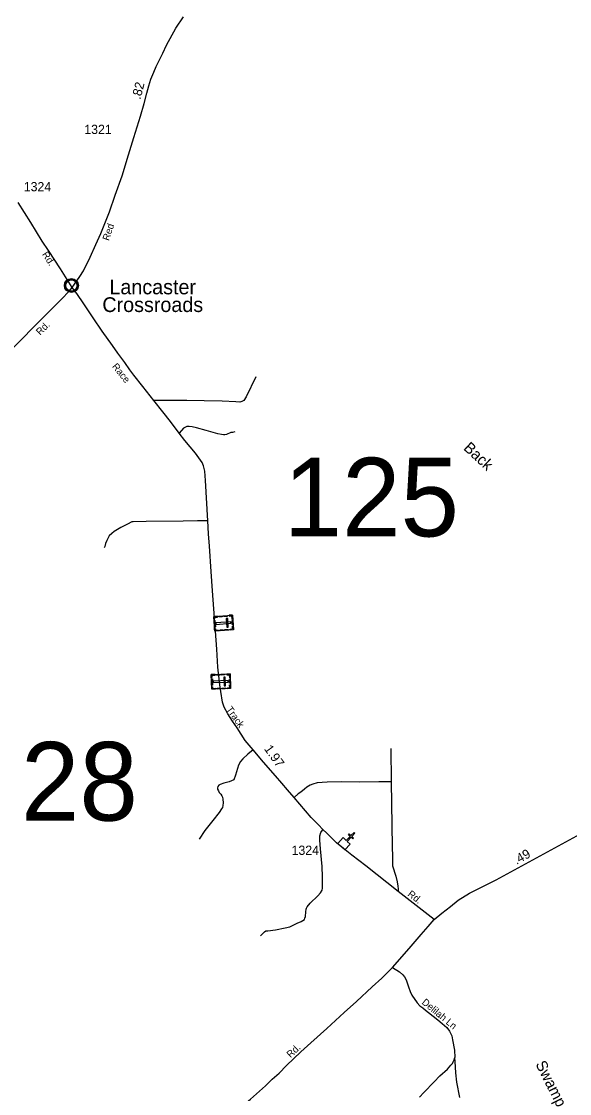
# Model space of a CAD drawing. Extents: x 2220236 to 2384410, y 720751 to 894131.
# Drawn here: x 2270444 to 2277880, y 831981 to 846519 of the extents above; entities that cross this region are included whole.
import ezdxf

# ---------------------------------------------------------------- set-up
doc = ezdxf.new("R2010")
doc.units = 0
doc.layers.add('Default', color=7, linetype='Continuous')

msp = doc.modelspace()

# ---------------------------------------------------------------- linework, layer by layer
at = {"layer": 'Default'}
msp.add_line((2275457, 836661), (2275461, 836207), dxfattribs=at)
for points in [[(2271133, 842913), (2271166, 842957), (2271237, 843061), (2271284, 843139), (2271378, 843322), (2271452, 843494), (2271520, 843644), (2271639, 843936), (2271717, 844164), (2271812, 844426), (2271898, 844711), (2271968, 844945), (2272015, 845092), (2272058, 845233), (2272107, 845406), (2272147, 845548), (2272172, 845646), (2272201, 845738), (2272239, 845832), (2272272, 845910), (2272362, 846091), (2272414, 846196), (2272538, 846429), (2272643, 846583)], [(2271133, 842913), (2270972, 843165), (2270812, 843415), (2270726, 843540), (2270574, 843793), (2270401, 844062)], [(2268432, 839884), (2268447, 839914), (2268479, 839958), (2268522, 840025), (2268605, 840135), (2268829, 840415), (2268931, 840536), (2269007, 840629), (2269178, 840846), (2269254, 840937), (2269443, 841177), (2269642, 841393), (2269800, 841551), (2269954, 841710), (2270098, 841859), (2270245, 842006), (2270400, 842161), (2270653, 842420), (2270813, 842577), (2270938, 842704), (2271017, 842782), (2271063, 842833), (2271095, 842865), (2271133, 842913)], [(2276045, 834343), (2275553, 834723), (2275115, 835071), (2274925, 835214), (2274815, 835303), (2274719, 835379), (2274581, 835517), (2274539, 835559), (2274471, 835628), (2274376, 835724), (2274142, 835997), (2274055, 836098), (2273978, 836191), (2273889, 836291), (2273727, 836474), (2273589, 836640), (2273481, 836769), (2273369, 836941), (2273306, 837029), (2273245, 837128), (2273196, 837220), (2273172, 837289), (2273147, 837431), (2273135, 837522), (2273108, 837763), (2273093, 838008), (2273036, 838800), (2273020, 839061), (2272996, 839402), (2272984, 839569), (2272972, 839749), (2272942, 840293), (2272932, 840423), (2272915, 840493), (2272895, 840540), (2272873, 840570), (2272807, 840665), (2272734, 840752), (2272659, 840837), (2272582, 840936), (2272465, 841094), (2272363, 841227), (2272242, 841380), (2272091, 841570), (2271969, 841724), (2271917, 841795), (2271847, 841895), (2271754, 842019), (2271679, 842124), (2271541, 842321), (2271416, 842498), (2271292, 842689), (2271195, 842828), (2271133, 842913)], [(2273622, 841702), (2273491, 841427), (2273460, 841378), (2273434, 841364), (2273405, 841358), (2273351, 841360), (2273169, 841368), (2272925, 841375), (2272690, 841381), (2272510, 841379), (2272242, 841380)], [(2273340, 840952), (2273308, 840945), (2273286, 840943), (2273226, 840919), (2273204, 840914), (2273184, 840914), (2273158, 840918), (2273110, 840929), (2272950, 840974), (2272819, 841007), (2272759, 841020), (2272718, 841028), (2272690, 841027), (2272642, 841006), (2272582, 840936)], [(2272972, 839749), (2272833, 839746), (2272639, 839741), (2272137, 839737), (2271961, 839736), (2271940, 839732), (2271882, 839701), (2271792, 839655), (2271703, 839603), (2271670, 839575), (2271636, 839544), (2271620, 839518), (2271602, 839482), (2271585, 839438), (2271575, 839400), (2271565, 839381)], [(2273589, 836640), (2273516, 836583), (2273448, 836518), (2273414, 836482), (2273389, 836435), (2273350, 836299), (2273325, 836234), (2273261, 836210), (2273192, 836189), (2273141, 836173), (2273123, 836161), (2273109, 836145), (2273105, 836126), (2273105, 836108), (2273117, 836084), (2273127, 836065), (2273147, 836043), (2273164, 836018), (2273174, 836000), (2273178, 835974), (2273182, 835923), (2273178, 835888), (2273172, 835862), (2273160, 835842), (2273125, 835791), (2273042, 835685), (2272932, 835547), (2272855, 835429)], [(2275461, 836207), (2275293, 836208), (2275032, 836205), (2274784, 836207), (2274590, 836203), (2274456, 836194), (2274396, 836177), (2274360, 836161), (2274314, 836135), (2274283, 836110), (2274233, 836068), (2274199, 836046), (2274142, 835997)], [(2275461, 836207), (2275472, 835326), (2275477, 835196), (2275476, 835106), (2275480, 835068), (2275523, 834930), (2275542, 834853), (2275552, 834793), (2275555, 834759), (2275553, 834723)], [(2273689, 834121), (2273731, 834166), (2273742, 834174), (2273760, 834187), (2273789, 834187), (2273889, 834203), (2274024, 834227), (2274084, 834240), (2274132, 834266), (2274184, 834290), (2274237, 834314), (2274263, 834327), (2274282, 834340), (2274290, 834358), (2274298, 834382), (2274303, 834445), (2274306, 834480), (2274311, 834496), (2274319, 834514), (2274361, 834564), (2274466, 834662), (2274500, 834701), (2274522, 834738), (2274527, 834767), (2274529, 834822), (2274529, 834920), (2274524, 835062), (2274500, 835299), (2274490, 835418), (2274494, 835476), (2274504, 835521), (2274528, 835552), (2274539, 835559)], [(2276045, 834343), (2276146, 834426), (2276264, 834519), (2276369, 834605), (2276521, 834700), (2276882, 834881), (2278077, 835532), (2278265, 835637)], [(2273329, 831730), (2273382, 831770), (2273431, 831804), (2273550, 831905), (2273753, 832085), (2273846, 832174), (2273941, 832259), (2274038, 832362), (2274234, 832545), (2274369, 832669), (2274589, 832865), (2274824, 833080), (2274991, 833229), (2275203, 833428), (2275332, 833545), (2275404, 833619), (2275477, 833691), (2275706, 833949), (2275869, 834136), (2275962, 834245), (2276045, 834343)], [(2275477, 833691), (2275573, 833630), (2275619, 833593), (2275640, 833563), (2275658, 833530), (2275667, 833508), (2275693, 833426), (2275719, 833364), (2275742, 833313), (2275812, 833213), (2275849, 833171), (2275889, 833143), (2275924, 833113), (2275966, 833080), (2276092, 832980), (2276153, 832930), (2276213, 832876), (2276251, 832825), (2276281, 832763), (2276293, 832711), (2276319, 832569), (2276324, 832468)], [(2275844, 831930), (2275901, 831995), (2276041, 832141), (2276122, 832222), (2276222, 832312), (2276271, 832364), (2276290, 832387), (2276301, 832412), (2276313, 832440), (2276324, 832468)], [(2276391, 831926), (2276352, 832136), (2276336, 832263), (2276327, 832416), (2276324, 832468)]]:
    msp.add_lwpolyline(points, dxfattribs=at)
for points in [[(2271044, 842950), (2271045, 842956), (2271047, 842962), (2271050, 842970), (2271053, 842975), (2271056, 842981), (2271060, 842986), (2271064, 842991), (2271069, 842995), (2271074, 843000), (2271080, 843003), (2271084, 843006), (2271090, 843009), (2271095, 843011), (2271101, 843013), (2271105, 843014), (2271110, 843015), (2271114, 843016), (2271120, 843016), (2271125, 843016), (2271130, 843015), (2271135, 843015), (2271140, 843014), (2271145, 843012), (2271150, 843010), (2271157, 843007), (2271163, 843004), (2271168, 843000), (2271174, 842996), (2271177, 842993), (2271181, 842989), (2271185, 842984), (2271188, 842980), (2271191, 842975), (2271193, 842969), (2271196, 842964), (2271197, 842959), (2271198, 842955), (2271199, 842949), (2271200, 842944), (2271200, 842938), (2271200, 842932), (2271200, 842927), (2271199, 842921), (2271197, 842915), (2271195, 842909), (2271193, 842904), (2271190, 842898), (2271186, 842893), (2271183, 842888), (2271179, 842883), (2271173, 842878), (2271168, 842874), (2271163, 842871), (2271159, 842868), (2271152, 842865), (2271145, 842862), (2271139, 842861), (2271133, 842860), (2271128, 842859), (2271124, 842859), (2271118, 842859), (2271114, 842859), (2271108, 842860), (2271102, 842861), (2271098, 842863), (2271092, 842864), (2271088, 842866), (2271084, 842869), (2271077, 842873), (2271072, 842877), (2271067, 842881), (2271062, 842886), (2271059, 842890), (2271056, 842894), (2271052, 842902), (2271050, 842905), (2271048, 842909), (2271046, 842917), (2271044, 842924), (2271044, 842930), (2271043, 842936), (2271043, 842941), (2271044, 842947)], [(2273307, 838469), (2273321, 838270), (2273067, 838252), (2273053, 838450)], [(2273055, 838417), (2273067, 838418), (2273065, 838440), (2273105, 838443), (2273105, 838454), (2273053, 838450)], [(2273122, 838455), (2273166, 838458), (2273166, 838447), (2273123, 838444)], [(2273190, 838460), (2273233, 838463), (2273234, 838452), (2273190, 838449)], [(2273242, 838423), (2273223, 838422), (2273232, 838304), (2273250, 838306)], [(2273263, 838466), (2273264, 838454), (2273296, 838457), (2273299, 838416), (2273310, 838417), (2273307, 838469)], [(2273068, 838394), (2273075, 838309), (2273063, 838308), (2273057, 838393)], [(2273065, 838285), (2273076, 838285), (2273078, 838263), (2273118, 838266), (2273119, 838255), (2273067, 838252)], [(2273285, 838358), (2273284, 838377), (2273082, 838362), (2273083, 838343)], [(2273204, 838273), (2273248, 838276), (2273248, 838265), (2273205, 838262)], [(2273278, 838267), (2273277, 838278), (2273309, 838281), (2273306, 838321), (2273317, 838322), (2273321, 838270)], [(2273312, 838395), (2273316, 838343), (2273305, 838342), (2273301, 838394)], [(2273139, 838268), (2273182, 838271), (2273183, 838260), (2273139, 838257)], [(2273274, 837671), (2273282, 837472), (2273027, 837463), (2273020, 837662)], [(2273021, 837629), (2273033, 837629), (2273032, 837651), (2273072, 837653), (2273072, 837664), (2273020, 837662)], [(2273034, 837605), (2273037, 837520), (2273025, 837520), (2273022, 837605)], [(2273249, 837561), (2273249, 837580), (2273046, 837573), (2273047, 837554)], [(2273090, 837665), (2273133, 837666), (2273134, 837655), (2273090, 837653)], [(2273157, 837667), (2273200, 837669), (2273201, 837657), (2273158, 837656)], [(2273208, 837628), (2273189, 837627), (2273194, 837510), (2273212, 837510)], [(2273231, 837670), (2273232, 837658), (2273264, 837659), (2273265, 837619), (2273276, 837619), (2273274, 837671)], [(2273277, 837597), (2273279, 837545), (2273268, 837545), (2273266, 837597)], [(2273026, 837496), (2273038, 837497), (2273038, 837475), (2273079, 837476), (2273079, 837465), (2273027, 837463)], [(2273099, 837477), (2273142, 837479), (2273143, 837467), (2273100, 837466)], [(2273165, 837479), (2273208, 837481), (2273209, 837470), (2273165, 837468)], [(2273238, 837471), (2273238, 837482), (2273270, 837483), (2273269, 837524), (2273280, 837524), (2273282, 837472)], [(2274810, 835451), (2274851, 835412), (2274904, 835468), (2274880, 835490), (2274891, 835501), (2274914, 835479), (2274956, 835523), (2274967, 835512), (2274926, 835468), (2274949, 835446), (2274939, 835435), (2274915, 835457), (2274863, 835401), (2274905, 835362), (2274832, 835284), (2274737, 835374)]]:
    msp.add_lwpolyline(points, close=True, dxfattribs=at)
for radius in [94.3, 76.7]:
    msp.add_circle((2271122, 842938), radius, dxfattribs=at)

# ---------------------------------------------------------------- texts
for s, height, rotation, p in [('.82', 125, 75.5648, (2272058, 845454)), ('Red', 95, 71.3489, (2271630, 843539)), ('Rd.', 95, 303.0632, (2270720, 843361)), ('Rd.', 95, 44.8836, (2270699, 842258)), ('Race', 95, 309.001, (2271668, 841838)), ('Back', 150, 317.2584, (2276431, 840722)), ('Track', 95, 304.942, (2273217, 837191)), ('1.97', 125, 305.4749, (2273730, 836655)), ('.49', 125, 29.0737, (2277160, 835082)), ('Rd.', 95, 322.094, (2275675, 834670)), ('Delilah Ln', 95, 320.3263, (2275867, 833205)), ('Rd.', 95, 43.1614, (2274095, 832460)), ('Swamp', 150, 296.6343, (2277414, 832382))]:
    msp.add_text(s, height=height, rotation=rotation, dxfattribs=at).set_placement(p)
for s, height, p in [('1321', 125, (2271297, 844993)), ('1324', 125, (2270476, 844216)), ('Lancaster', 200, (2271638, 842819)), ('Crossroads', 200, (2271542, 842579)), ('125', 1066.3, (2274001, 839536)), ('28', 1066.3, (2270438, 835682)), ('1324', 125, (2274109, 835218))]:
    msp.add_text(s, height=height, dxfattribs=at).set_placement(p)

doc.saveas('drawing.dxf')
